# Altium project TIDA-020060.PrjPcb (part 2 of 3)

## Sheet Board_ID_EEPROM.SchDoc
size A4; Date: Not shown in title block; ApprovedBy: Not shown in title block; CheckedBy: Not shown in title block; Author: Not shown in title block; CompanyName: Not shown in title block; Engineer: Not shown in title block; Organization: Not shown in title block; Address1: Not shown in title block; Address2: Not shown in title block; Address3: Not shown in title block; Address4: Not shown in title block; DocumentNumber: 4; Revision: Use project parameter SCH_Rev; SheetNumber: 4; SheetTotal: 19; PageSetup: Record=PageOptions¦CenterHorizontal=True¦CenterVertical=True¦PrintScale=0.93¦XCorrection=1.00¦YCorrection=1.00¦PrintKind=0¦BorderSize=5000000¦LeftOffset=0¦BottomOffset=0¦Orientation=2¦PaperLength=1000¦PaperWidth=1000¦Scale=100¦PaperSource=15¦PrintQuality=600¦MediaType=1¦DitherType=10¦PaperKind=Letter¦PrintScaleMode=1
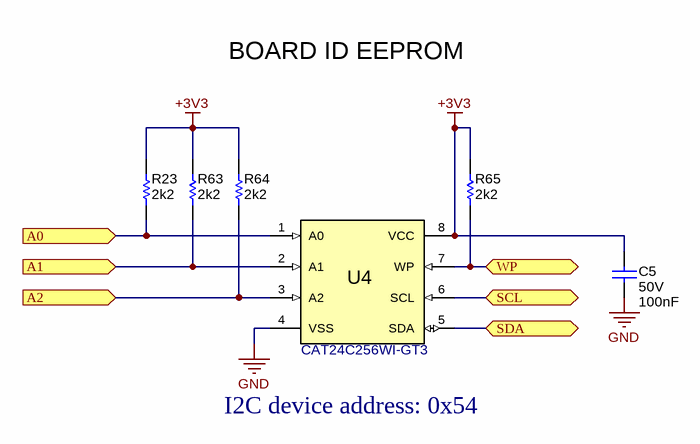
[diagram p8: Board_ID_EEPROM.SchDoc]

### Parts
C5  VDC_V: 50V  ValueDisplayed: 100nF  [0402]  (hidden comment: C1005X5R1H104K050BB)
R23  ValueDisplayed: 2k2  [0402]  (hidden comment: CRCW04022K20JNED)
R63  ValueDisplayed: 2k2  [0402]  (hidden comment: CRCW04022K20JNED)
R64  ValueDisplayed: 2k2  [0402]  (hidden comment: CRCW04022K20JNED)
R65  ValueDisplayed: 2k2  [0402]  (hidden comment: CRCW04022K20JNED)
U4  CAT24C256WI-GT3  [SOIC-8]

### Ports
A0 (in), A1 (in), A2 (in), SCL (bidir), SDA (bidir), WP (bidir)

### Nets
+3V3: C5.2 R23.2 R63.2 R64.2 R65.2 U4.8(VCC)
GND: C5.1 U4.4(VSS)
A0: R23.1 U4.1(A0) ; port A0
A1: R63.1 U4.2(A1) ; port A1
A2: R64.1 U4.3(A2) ; port A2
WKUP_I2C0_SCL: U4.6(SCL) ; port SCL
WKUP_I2C0_SDA: U4.5(SDA) ; port SDA
WP: R65.1 U4.7(WP) ; port WP

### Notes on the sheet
- BOARD ID EEPROM
- I2C device address: 0x54

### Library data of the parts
C5 = CMP-0006279-2: CAP, CERM, 0.1 uF, 50 V, +/- 10%, X5R, 0402; Manufacturer: TDK; TaMin_C: -55°C; ESR_ohm: 0.039064; Polarized: N; SizeAreaWB_mm2: 3; Value1: 0.039064 ohm; U/M: EA; Value: 0.1uF; TaMax_C: 85°C; SizeZ_mm: 0.6; SizeX_mm: 1; SizeY_mm: 0.5; IRMS_A: 814.669mA; AEC Category: Q200
R23 R63-R65 = CMP-0026890-5: RES, 2.2 k, 5%, 0.063 W, AEC-Q200 Grade 0, 0402; Manufacturer: Vishay-Dale; Power_W: 63mW; TempCo: 200 ppm/C; Value_Code: 2k20; Value: 2.2k; EIA_Code: E24; SizeX_mm: 1; SizeY_mm: 0.5; SizeZ_mm: 0.6; Value2: 0.063W; AEC Qualified: Y; VDC_V: 50V; AEC Category: Q200; AEC Grade: 0
U4 = CMP-0005313-2: 256 kb I2C CMOS Serial EEPROM, SOIC-8; Manufacturer: ON Semiconductor; SizeAreaWB_mm2: 55.131; SizeZ_mm: 1.75; SizeX_mm: 5.99; SizeY_mm: 4.9; SizeArea_mm2: 29.351

## Sheet SGMII_caps.SchDoc
size A4; Date: Not shown in title block; ApprovedBy: Not shown in title block; CheckedBy: Not shown in title block; Author: Not shown in title block; CompanyName: Not shown in title block; Engineer: Not shown in title block; Organization: Not shown in title block; Address1: Not shown in title block; Address2: Not shown in title block; Address3: Not shown in title block; Address4: Not shown in title block; DocumentNumber: 11; Revision: Use project parameter SCH_Rev; SheetNumber: 11; SheetTotal: 19; PageSetup: Record=PageOptions¦CenterHorizontal=True¦CenterVertical=True¦PrintScale=0.93¦XCorrection=1.00¦YCorrection=1.00¦PrintKind=0¦BorderSize=5000000¦LeftOffset=0¦BottomOffset=0¦Orientation=2¦PaperLength=1000¦PaperWidth=1000¦Scale=100¦PaperSource=15¦PrintQuality=600¦MediaType=1¦DitherType=10¦PaperKind=Letter¦PrintScaleMode=1
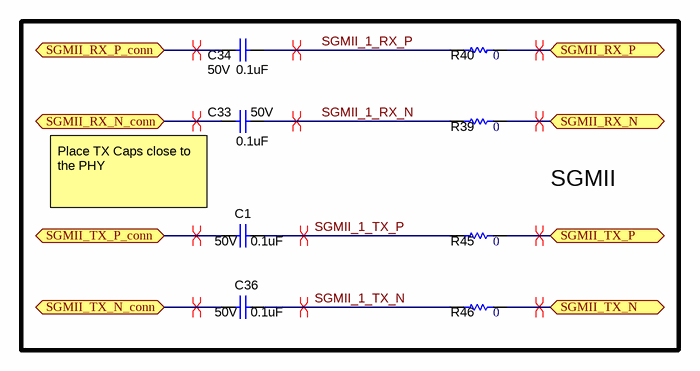
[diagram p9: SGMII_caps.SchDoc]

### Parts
C1  VDC_V: 50V  ValueDisplayed: 0.1uF  [0402S]  (hidden comment: C1005X5R1H104K050BB)
C33  VDC_V: 50V  ValueDisplayed: 0.1uF  [0402S]  (hidden comment: C1005X5R1H104K050BB)
C34  VDC_V: 50V  ValueDisplayed: 0.1uF  [0402S]  (hidden comment: C1005X5R1H104K050BB)
C36  VDC_V: 50V  ValueDisplayed: 0.1uF  [0402S]  (hidden comment: C1005X5R1H104K050BB)
R39  ValueDisplayed: 0  [0402S]  (hidden comment: RK73Z1ETTP)
R40  ValueDisplayed: 0  [0402S]  (hidden comment: RK73Z1ETTP)
R45  ValueDisplayed: 0  [0402S]  (hidden comment: RK73Z1ETTP)
R46  ValueDisplayed: 0  [0402S]  (hidden comment: RK73Z1ETTP)

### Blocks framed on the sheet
SGMII: C1 C33 C34 C36 R39 R40 R45 R46

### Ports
SGMII_RX_N (bidir), SGMII_RX_N_conn (bidir), SGMII_RX_P (bidir), SGMII_RX_P_conn (bidir), SGMII_TX_N (bidir), SGMII_TX_N_conn (bidir), SGMII_TX_P (bidir), SGMII_TX_P_conn (bidir)

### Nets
AE_RX_N: R39.2 ; port SGMII_RX_N
AE_RX_P: R40.2 ; port SGMII_RX_P
AE_TX_N: R46.2 ; port SGMII_TX_N
AE_TX_P: R45.2 ; port SGMII_TX_P
SGMII_1_RX_N: C33.2 R39.1
SGMII_1_RX_P: C34.2 R40.1
SGMII_1_TX_N: C36.2 R46.1
SGMII_1_TX_P: C1.2 R45.1
SGMII_2_RX_N: C33.1 ; port SGMII_RX_N_conn
SGMII_2_RX_P: C34.1 ; port SGMII_RX_P_conn
SGMII_2_TX_N: C36.1 ; port SGMII_TX_N_conn
SGMII_2_TX_P: C1.1 ; port SGMII_TX_P_conn

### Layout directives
differential pair: AE_RX_N, AE_RX_P, AE_TX_N, AE_TX_P, SGMII_1_RX_N, SGMII_1_RX_P, SGMII_1_TX_N, SGMII_1_TX_P, SGMII_2_RX_N, SGMII_2_RX_P, SGMII_2_TX_N, SGMII_2_TX_P

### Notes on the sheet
- Place TX Caps close to the PHY

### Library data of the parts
C1 C33 C34 C36 = CMP-0006279-2: CAP, CERM, 0.1 uF, 50 V, +/- 10%, X5R, 0402; Manufacturer: TDK; TaMin_C: -55°C; ESR_ohm: 39.064m; Polarized: N; SizeAreaWB_mm2: 3; Value1: 0.039064 ohm; U/M: EA; Value: 0.1uF; TaMax_C: 85°C; SizeZ_mm: 0.6; SizeX_mm: 1; SizeY_mm: 0.5; Cap_Case: 0402; Cap_F: 100nF; IRMS_A: 814.669mA; AEC Category: Q200
R39 R40 R45 R46 = CMP-0027007-2: RES, 0, 5%, 0.063 W, AEC-Q200 Grade 0, 0402; Manufacturer: KOA Speer; Power_W: 63mW; TempCo: ppm/C; Value_Code: 0000; Value: 0; SizeX_mm: 1; SizeY_mm: 0.5; SizeZ_mm: 0.6; Value2: 0.063W; AEC Qualified: Y; AEC Category: Q200; EIA_Code: E24; U/M: EA

## Sheet power_indicator_LEDs.SchDoc
size A4; Date: Not shown in title block; ApprovedBy: Not shown in title block; CheckedBy: Not shown in title block; Author: Not shown in title block; CompanyName: Not shown in title block; Engineer: Not shown in title block; Organization: Not shown in title block; Address1: Not shown in title block; Address2: Not shown in title block; Address3: Not shown in title block; Address4: Not shown in title block; DocumentNumber: 12; Revision: Use project parameter SCH_Rev; SheetNumber: 12; SheetTotal: 19; PageSetup: Record=PageOptions¦CenterHorizontal=True¦CenterVertical=True¦PrintScale=0.93¦XCorrection=1.00¦YCorrection=1.00¦PrintKind=0¦BorderSize=5000000¦LeftOffset=0¦BottomOffset=0¦Orientation=2¦PaperLength=1000¦PaperWidth=1000¦Scale=100¦PaperSource=15¦PrintQuality=600¦MediaType=1¦DitherType=10¦PaperKind=Letter¦PrintScaleMode=1
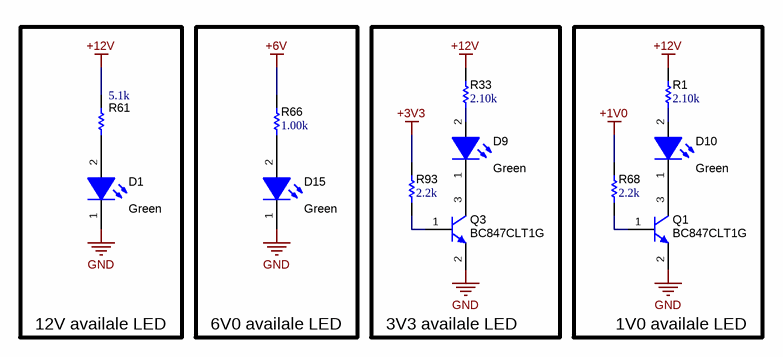
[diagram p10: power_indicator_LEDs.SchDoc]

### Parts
D1  value Green  [LG_M67K_Green]  (hidden comment: LG M67K-G1J2-24-Z)
D9  value Green  [LG_M67K_Green]  (hidden comment: LG M67K-G1J2-24-Z)
D10  value Green  [LG_M67K_Green]  (hidden comment: LG M67K-G1J2-24-Z)
D15  value Green  [LG_M67K_Green]  (hidden comment: LG M67K-G1J2-24-Z)
Q1  BC847CLT1G  [SOT-23]
Q3  BC847CLT1G  [SOT-23]
R1  ValueDisplayed: 2.10k  [0805_HV]  (hidden comment: CRCW08052K10FKEA)
R33  ValueDisplayed: 2.10k  [0805_HV]  (hidden comment: CRCW08052K10FKEA)
R61  Res_ohm: 5.1k  [0805M]  (hidden comment: CRCW08055K10JNEA)
R66  ValueDisplayed: 1.00k  [0805_HV]  (hidden comment: CRCW08051K00FKEA)
R68  ValueDisplayed: 2.2k  [0402]  (hidden comment: CRCW04022K20JNED)
R93  ValueDisplayed: 2.2k  [0402]  (hidden comment: CRCW04022K20JNED)

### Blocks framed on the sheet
12V availale LED: D1 R61
6V0 availale LED: D15 R66
3V3 availale LED: D9 Q3 R33 R93
1V0 availale LED: D10 Q1 R1 R68

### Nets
+1V0: R68.1
+3V3: R93.1
+6V: R66.2
+12V: R1.2 R33.2 R61.2
GND: D1.1(K) D15.1(K) Q1.2(E) Q3.2(E)
NetD1_2: D1.2(A) R61.1
NetD9_1: D9.1(K) Q3.3(C)
NetD9_2: D9.2(A) R33.1
NetD10_1: D10.1(K) Q1.3(C)
NetD10_2: D10.2(A) R1.1
NetD15_2: D15.2(A) R66.1
NetQ1_1: Q1.1(B) R68.2
NetQ3_1: Q3.1(B) R93.2

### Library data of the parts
D1 D9 D10 D15 = CMP-0002971-3: LED, Green, SMD; Manufacturer: OSRAM; Value2: 1.8V; Type: AlInGaP; Io_A: 2mA; Tjmax_C: 125°C; Value1: W; Vr_V: 12V; Angle: 120
Q1 Q3 = CMP-0000376-2: Transistor, NPN, 45 V, 0.1 A, SOT-23; Manufacturer: ON Semiconductor; TaMax_C: 150°C; Value2: 800; Value1: 0.1 A; Vcesat1_V: 7dV; SizeX_mm: 2.5; SizeY_mm: 3; TaMin_C: -55°C; IcRated_A: 1dA; CompType: BJT; SizeZ_mm: 1.1; Value: 45 V; SizeArea_mm2: 7.5; NPN: 1; Vceo_V: 45V; PNP: 0; AEC Category: Q101; SizeAreaWB_mm2: 14; U/M: EA
R1 R33 = CMP-0021108-3: RES, 2.10 k, 1%, 0.125 W, AEC-Q200 Grade 0, 0805; Manufacturer: Vishay-Dale; Power_W: 125mW; TempCo: 100 ppm/C; Value_Code: 2k10; Value: 2.10k; EIA_Code: E96; Res_ohm: 2.1k; SizeX_mm: 2; SizeY_mm: 1.25; SizeZ_mm: 1.45; Value2: 0.125W; SizeArea_mm2: 2.5; AEC Qualified: Y; VDC_V: 150V; AEC Category: Q200; AEC Grade: 0
R61 = CMP-0020572-3: RES, 5.1 k, 5%, 0.125 W, AEC-Q200 Grade 0, 0805; Manufacturer: Vishay-Dale; Power_W: 125mW; TempCo: 200 ppm/C; SizeZ_mm: 1.45; AEC Qualified: Y; VDC_V: 150V; AEC Grade: 0; AEC Category: Q200; EIA_Code: E24; SizeArea_mm2: 2.5; SizeX_mm: 2; SizeY_mm: 1.25; Value2: 0.125W; Value: 5.1k; Value_Code: 5k10
R66 = CMP-0020951-3: RES, 1.00 k, 1%, 0.125 W, AEC-Q200 Grade 0, 0805; Manufacturer: Vishay-Dale; Power_W: 125mW; TempCo: 100 ppm/C; Value_Code: 1k00; Value: 1.00k; EIA_Code: E96; Res_ohm: 1k; SizeX_mm: 2; SizeY_mm: 1.25; SizeZ_mm: 1.45; Value2: 0.125W; SizeArea_mm2: 2.5; AEC Qualified: Y; VDC_V: 150V; AEC Category: Q200; AEC Grade: 0
R68 R93 = CMP-0026890-5: as R23 on sheet Board_ID_EEPROM

## Sheet 1V0_LDO.SchDoc
size A4; Date: Not shown in title block; ApprovedBy: Not shown in title block; CheckedBy: Not shown in title block; Author: Not shown in title block; CompanyName: Not shown in title block; Engineer: Not shown in title block; Organization: Not shown in title block; Address1: Not shown in title block; Address2: Not shown in title block; Address3: Not shown in title block; Address4: Not shown in title block; DocumentNumber: 10; Revision: Use project parameter SCH_Rev; SheetNumber: 10; SheetTotal: 19; PageSetup: Record=PageOptions¦CenterHorizontal=True¦CenterVertical=True¦PrintScale=0.93¦XCorrection=1.00¦YCorrection=1.00¦PrintKind=0¦BorderSize=5000000¦LeftOffset=0¦BottomOffset=0¦Orientation=2¦PaperLength=1000¦PaperWidth=1000¦Scale=100¦PaperSource=15¦PrintQuality=600¦MediaType=1¦DitherType=10¦PaperKind=Letter¦PrintScaleMode=1
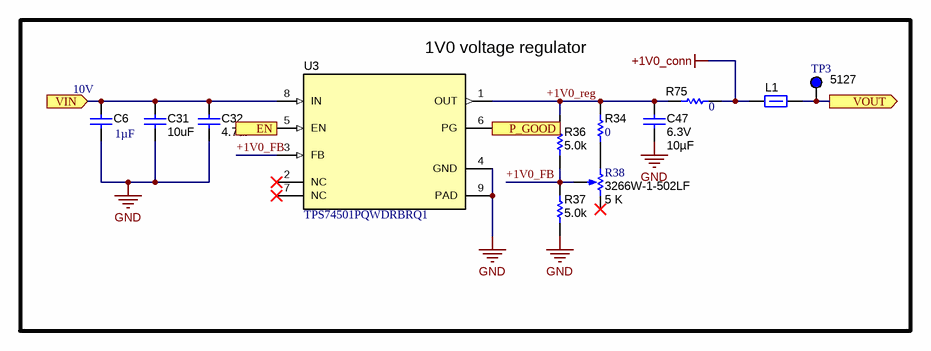
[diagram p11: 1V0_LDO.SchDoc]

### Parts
C6  ValueDisplayed: 1µF  VDC_V: 10V  [0402]  (hidden comment: GRT155C71A105KE13D)
C31  ValueDisplayed: 10uF  [0805_HV]  (hidden comment: GRM21BC71E106KE11L)
C32  ValueDisplayed: 4.7uF  [0603]  (hidden comment: C1608X7S1A475K080AC)
C47  VDC_V: 6.3V  Cap_F: 10µF  [0603]  (hidden comment: CL10B106MQ8NRNC)
L1  BLM18AG102SN1D  [0603]  (value not drawn)
R34  ValueDisplayed: 0  [0402]  (hidden comment: RK73Z1ETTP)
R36  ValueDisplayed: 5.0k  [0402]  (hidden comment: CRCW04024K42FKED)
R37  ValueDisplayed: 5.0k  [0402]  (hidden comment: CRCW04024K42FKED)
R38  3266W-1-502LF  value 5 K  [TRIM_3266W]
R75  ValueDisplayed: 0  [0402]  (hidden comment: RK73Z1ETTP)
TP3  5127  [Keystone5127]
U3  TPS74501PQWDRBRQ1  [DRB0008J]

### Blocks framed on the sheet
1V0 voltage regulator: C6 C31 C32 C47 L1 R34 R36-R38 R75 TP3 U3

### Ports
EN (in), P_GOOD (out), VIN (in), VOUT (out)

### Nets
+1V0: L1.2 TP3.1 ; port VOUT
+1V0_conn: L1.1 R75.2
+3V3: C6.1 C31.2 C32.2 U3.5(EN) U3.8(IN) ; port VIN, port EN
GND: C6.2 C31.1 C32.1 C47.2 R37.1 U3.4(GND) U3.9(PAD)
+1V0_FB: R36.1 R37.2 R38.2(WIPER) U3.3(FB)
+1V0_reg: C47.1 R34.1 R36.2 R75.1 U3.1(OUT)
PG_1V: U3.6(PG) ; port P_GOOD
NetR34_2: R34.2 R38.1(CCW)

Not connected (* = marked no-connect by the designer): R38 3(CW)*; U3 2(NC)* 7(NC)*

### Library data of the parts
C6 = CMP-0085818-1: CAP, CERM, 1 µF, 10 V,+/- 10%, X7S, AEC-Q200 Grade 1, 0402; Manufacturer: MuRata; TaMin_C: -55°C; Polarized: N; SizeAreaWB_mm2: 3; U/M: EA; Value: 1uF; TaMax_C: 125°C; SizeZ_mm: 0.6; SizeX_mm: 1; SizeY_mm: 0.5; AEC Qualified: Y; AEC Category: Q200
C31 = CMP-0008262-2: CAP, CERM, 10 uF, 25 V, +/- 10%, X7S, 0805; Manufacturer: MuRata; TaMin_C: -55°C; Polarized: N; SizeAreaWB_mm2: 6.75; Value1: Unknown; U/M: EA; Value: 10uF; TaMax_C: 125°C; SizeZ_mm: 1.45; SizeX_mm: 2; SizeY_mm: 1.25; Cap_Case: 0805; Value2: 25V; SizeArea_mm2: 2.5; Cap_F: 10µF; AEC Category: Q200
C32 = CMP-0007058-4: CAP, CERM, 4.7 uF, 10 V, +/- 10%, X7S, 0603; Manufacturer: TDK; TaMin_C: -55°C; Polarized: N; SizeAreaWB_mm2: 4.68; Value1: Unknown; U/M: EA; Value: 4.7uF; TaMax_C: 125°C; SizeZ_mm: 1; SizeX_mm: 1.6; SizeY_mm: 0.8; Value2: 10V; SizeArea_mm2: 1.28; Cap_F: 4.7µF; AEC Category: Q200
C47 = CMP-0084301-1: CAP, CERM, 10 µF, 6.3 V,+/- 20%, X7R, 0603; Manufacturer: Samsung Electro-Mechanics; SizeY_mm: 0.8; SizeAreaWB_mm2: 4.68; SizeX_mm: 1.6; SizeArea_mm2: 1.28; AEC Qualified: N; Value: 10uF; U/M: EA; SizeZ_mm: 1; TaMax_C: 125°C; AEC Category: Q200; TaMin_C: -55°C
L1 = CMP-0003343-2: Ferrite Bead, 1000 ohm @ 100 MHz, 0.4 A, 0603; Manufacturer: MuRata; ZTyp@100MHz_Ohm: 1k; SizeAreaWB_mm2: 4.68; DCR_ohm: 0.5; Value1: 0.5 ohm; Imax_A: 400mA; SizeZ_mm: 1; SizeX_mm: 1.6; SizeY_mm: 0.8; Value2: 0.4A; SizeArea_mm2: 1.28
R34 R75 = CMP-0027007-2: RES, 0, 5%, 0.063 W, AEC-Q200 Grade 0, 0402; Manufacturer: KOA Speer; Power_W: 63mW; TempCo: ppm/C; Value_Code: 0000; Value: 0; EIA_Code: E24; SizeX_mm: 1; SizeY_mm: 0.5; SizeZ_mm: 0.6; Value2: 0.063W; AEC Qualified: Y; AEC Category: Q200; U/M: EA
R36 R37 = CMP-0026409-2: RES, 5.0k, 1%, 0.063 W, AEC-Q200 Grade 0, 0402; Manufacturer: Vishay-Dale; Power_W: 63mW; TempCo: 100 ppm/C; Value_Code: 4k42; EIA_Code: E96; Res_ohm: 4.42k; SizeX_mm: 1; SizeY_mm: 0.5; SizeZ_mm: 0.6; Value2: 0.063W; AEC Qualified: Y; VDC_V: 50V; AEC Category: Q200; AEC Grade: 0
R38 = CMP-0002067-2: Trimmer, 5k ohm, 0.25W, TH; Manufacturer: Bourns
TP3 = CMP-0055156-2: Test Point, Multipurpose, Blue, TH; Manufacturer: Keystone Electronics; CNHeader: FALSE; Green_Lifecycle: Active; Green_REACh: Passed; ContactFinish: Silver; CT: TRUE
U3 = CMP-0860764-1: 500-mA LDO With Power-Good in Small Wettable Flank WSON Package, DRB0008J (VSON-8); Manufacturer: Texas Instruments; SizeZ_mm: 1; SizeAreaWB_mm2: 16; CompType: IC; SizeArea_mm2: 9; SizeY_mm: 3; AEC Category: Q200; AEC Qualified: Y

## Sheet PSE.SchDoc
size A4; Date: Not shown in title block; ApprovedBy: Not shown in title block; CheckedBy: Not shown in title block; Author: Not shown in title block; CompanyName: Not shown in title block; Engineer: Not shown in title block; Organization: Not shown in title block; Address1: Not shown in title block; Address2: Not shown in title block; Address3: Not shown in title block; Address4: Not shown in title block; DocumentNumber: 14; Revision: Use project parameter SCH_Rev; SheetNumber: 14; SheetTotal: 19; PageSetup: Record=PageOptions¦CenterHorizontal=True¦CenterVertical=True¦PrintScale=0.93¦XCorrection=1.00¦YCorrection=1.00¦PrintKind=0¦BorderSize=5000000¦LeftOffset=0¦BottomOffset=0¦Orientation=2¦PaperLength=1000¦PaperWidth=1000¦Scale=100¦PaperSource=15¦PrintQuality=600¦MediaType=1¦DitherType=10¦PaperKind=Letter¦PrintScaleMode=1
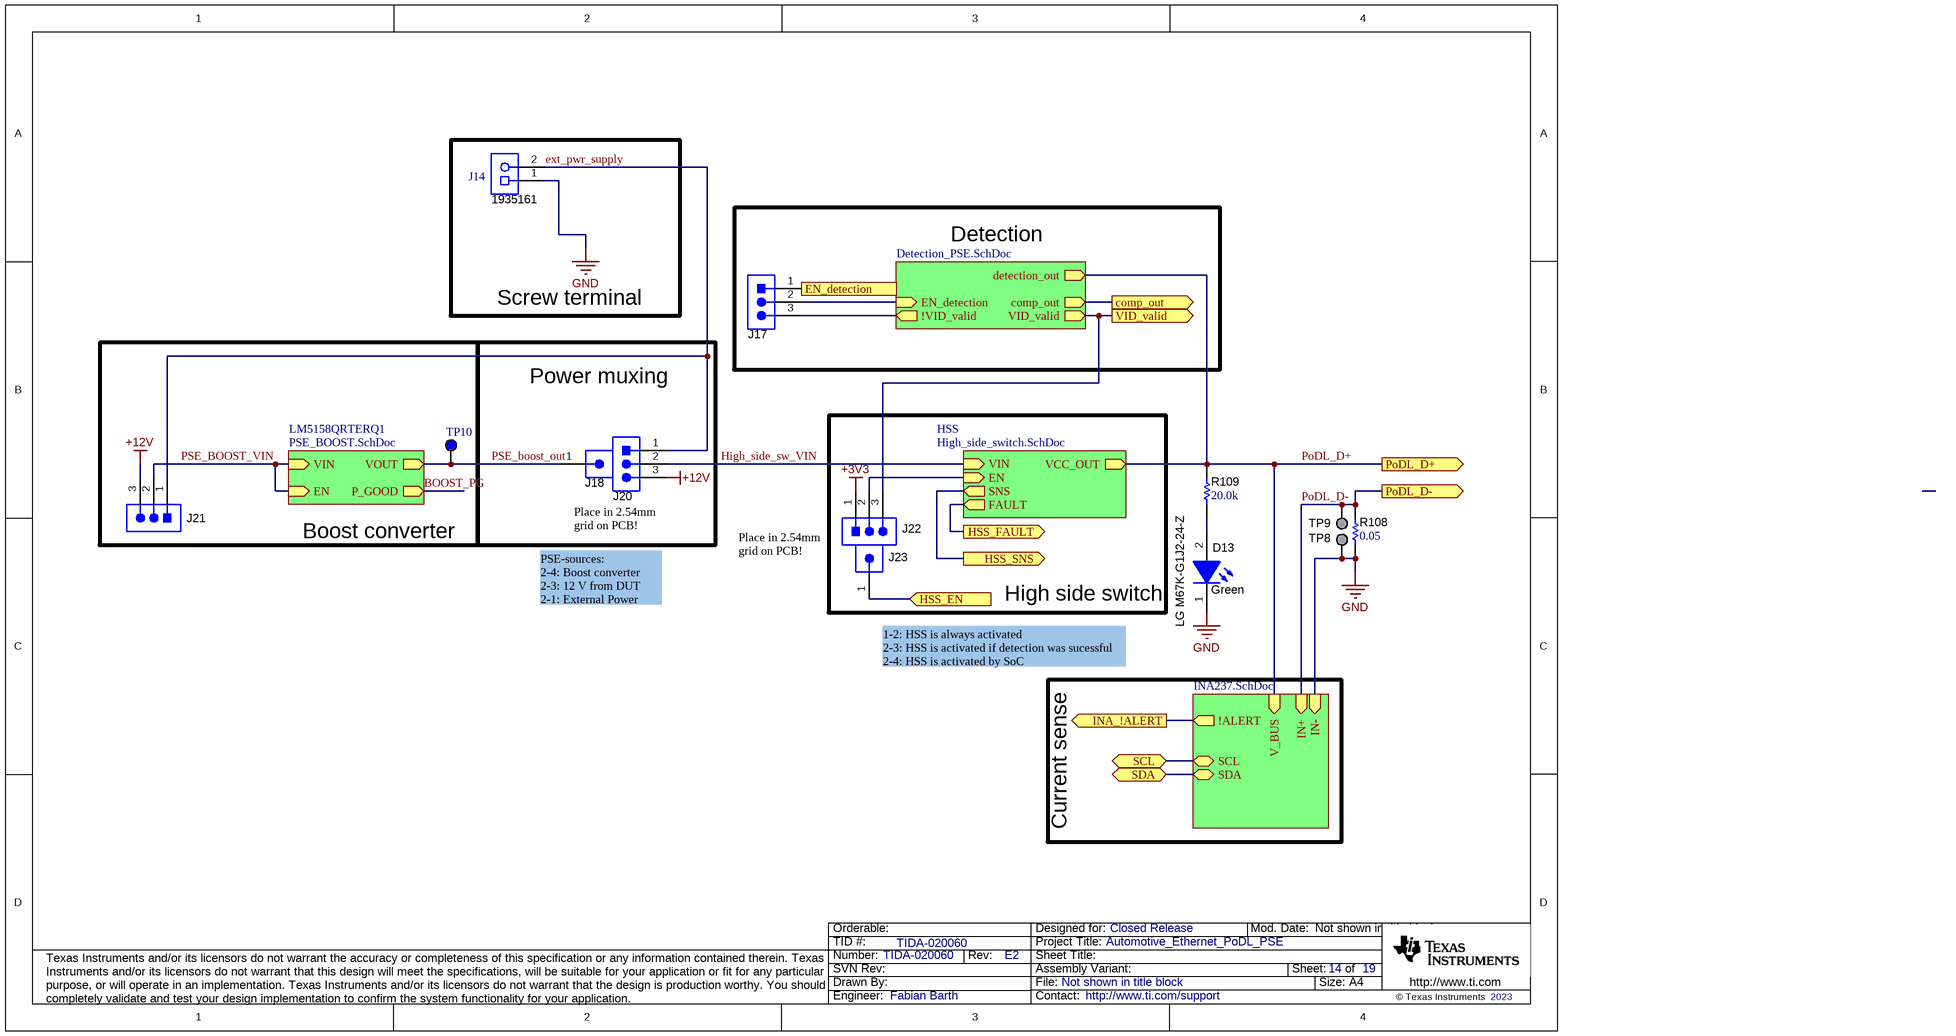
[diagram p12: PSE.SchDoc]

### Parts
D13  LG M67K-G1J2-24-Z  value Green  [LG_M67K_Green]
J14  1935161  [Phoenix_1935161]
J17  TSW-103-07-G-S  [TSW-103-07-G-S]  (value not drawn)
J18  TSW-101-07-G-S  [TSW-101-07-G-S]  (value not drawn)
J20  TSW-103-07-G-S  [TSW-103-07-G-S]  (value not drawn)
J21  TSW-103-07-G-S  [TSW-103-07-G-S]  (value not drawn)
J22  TSW-103-07-G-S  [TSW-103-07-G-S]  (value not drawn)
J23  TSW-101-07-G-S  [TSW-101-07-G-S]  (value not drawn)
R108  ValueDisplayed: 0.05  [0612]  (hidden comment: ERJ-B2CFR05V)
R109  ValueDisplayed: 20.0k  [0402]  (hidden comment: RT0402BRD0720KL)
TP8  TP_SM_1MM  [TP_SM_1MM]  (value not drawn)  (no BOM)
TP9  TP_SM_1MM  [TP_SM_1MM]  (value not drawn)  (no BOM)
TP10  5127  [Keystone5127]  (value not drawn)

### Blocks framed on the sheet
Screw terminal: J14
Detection: J17
Boost converter: J21 TP10
Power muxing: J18 J20
High side switch: J22 J23

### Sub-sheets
current_sense_sheet = INA237.SchDoc: IN+ (in), IN- (in), V_BUS (in), SDA (bidir), SCL (bidir), !ALERT (out)
Detections_sheet = Detection_PSE.SchDoc: detection_out (out), EN_detection (in), comp_out (out), !VID_valid (out), VID_valid (out)
HSS = High_side_switch.SchDoc: VIN (in), VCC_OUT (out), EN (in), FAULT (out), SNS (out)
LM5158QRTERQ1 = PSE_BOOST.SchDoc: EN (in), VIN (in), VOUT (out), P_GOOD (out)

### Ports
comp_out (out), EN_detection (out), HSS_EN (in), HSS_FAULT (out), HSS_SNS (out), INA_!ALERT (out), PoDL_D+ (out), PoDL_D- (out), SCL (bidir), SDA (bidir), VID_valid (out)

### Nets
+3V3: J22.1
+12V: J20.3 J21.3
GND: D13.1(K) J14.1 R108.1 TP8.1 ; sheet current_sense_sheet/IN-
!ALERT: port INA_!ALERT, sheet current_sense_sheet/!ALERT
comp_out: port comp_out, sheet Detections_sheet/comp_out
EN: J22.2 ; sheet HSS/EN
EN_detection: J17.2 ; sheet Detections_sheet/EN_detection
EN_detection_SoC: J17.1 ; port EN_detection
ext_pwr_supply: J14.2 J20.1 J21.1
High_side_sw_VIN: J20.2 ; sheet HSS/VIN
HSS_EN: J23.1 ; port HSS_EN
HSS_FAULT: port HSS_FAULT, sheet HSS/FAULT
HSS_SNS: port HSS_SNS, sheet HSS/SNS
PoDL_D+: R109.2 ; port PoDL_D+, sheet HSS/VCC_OUT, sheet Detections_sheet/detection_out, sheet current_sense_sheet/V_BUS
PoDL_D-: R108.2 TP9.1 ; port PoDL_D-, sheet current_sense_sheet/IN+
PSE_boost_out: J18.1 TP10.1 ; sheet LM5158QRTERQ1/VOUT
PSE_BOOST_VIN: J21.2 ; sheet LM5158QRTERQ1/EN, sheet LM5158QRTERQ1/VIN
Q: J22.3 ; port VID_valid, sheet Detections_sheet/VID_valid
Q_N: J17.3 ; sheet Detections_sheet/!VID_valid
SCL: port SCL, sheet current_sense_sheet/SCL
SDA: port SDA, sheet current_sense_sheet/SDA
NetD13_2: D13.2(A) R109.1

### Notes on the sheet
- Place in 2.54mm grid on PCB!
- PSE-sources:
  2-4: Boost converter
  2-3: 12 V from DUT
  2-1: External Power
- 1-2: HSS is always activated
  2-3: HSS is activated if detection was sucessful
  2-4: HSS is activated by SoC
- Current sense

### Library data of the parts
D13 = CMP-0002971-3: as D1 on sheet power_indicator_LEDs
J14 = CMP-0055502-1: Therminal Block, 5 mm, 2-pole, TH; Manufacturer: Phoenix Contact; CT: TRUE; CompType: Terminal Block; CNHeader: FALSE
J17 J20-J22 = CMP-0075407-2: Header, 100mil, 3x1, Gold, TH; Manufacturer: Samtec; Pitch_mm: 2.54; Cert_VDE: N; Gender: Male; Cert_CSA: Y; Voltage_V: 550V; Green_REACh: Passed; Current_A: 6.3A; Green_Lifecycle: Active; Row_Count: 1
J18 J23 = CMP-0075403-1: Header, 100mil, 1pos, Gold, TH; Manufacturer: Samtec; Cert_VDE: N; CNHeader: True; Current_A: 6.3A; Green_Lifecycle: Active; Gender: Male; Cert_CSA: Y; Green_REACh: Passed; Voltage_V: 550V; Row_Count: 1; Pitch_mm: 2.54; CT: False
R108 = CMP-0015056-3: RES, 0.05, 1%, 1 W, AEC-Q200 Grade 0, 0612; Manufacturer: Panasonic; Value: 0.05; Res_ohm: 50m; Power_W: 1W; SizeY_mm: 3.2; AEC Grade: 0; SizeArea_mm2: 5.12; SizeAreaWB_mm2: 10.92; AEC Category: Q200; TempCo: 150 ppm/C; SizeZ_mm: 0.85; SizeX_mm: 1.6; Value_Code: R050; AEC Qualified: Y; U/M: EA; EIA_Code: E96
R109 = CMP-0065358-1: RES, 20.0 k, .1%, .0625 W, 0402; Manufacturer: Yageo America; Power_W: 62.5mW; TempCo: 25 ppm/C; Value_Code: 20k0; U/M: EA; Value: 20.0k; EIA_Code: E192; Tolerance_%: 0.1%; Res_ohm: 20k; SizeX_mm: 1.0; SizeY_mm: 0.5; SizeZ_mm: 0.6; Value2: .0625W; VDC_V: 50V; AEC Category: Q200
TP8 TP9 = CMP-0003825-1: 1mm Test Point, SMT; Manufacturer: Any
TP10 = CMP-0055156-2: as TP3 on sheet 1V0_LDO

## Sheet High_side_switch.SchDoc
size A4; Date: Not shown in title block; ApprovedBy: Not shown in title block; CheckedBy: Not shown in title block; Author: Not shown in title block; CompanyName: Not shown in title block; Engineer: Not shown in title block; Organization: Not shown in title block; Address1: Not shown in title block; Address2: Not shown in title block; Address3: Not shown in title block; Address4: Not shown in title block; DocumentNumber: 18; Revision: Use project parameter SCH_Rev; SheetNumber: 18; SheetTotal: 19; PageSetup: Record=PageOptions¦CenterHorizontal=True¦CenterVertical=True¦PrintScale=0.93¦XCorrection=1.00¦YCorrection=1.00¦PrintKind=0¦BorderSize=5000000¦LeftOffset=0¦BottomOffset=0¦Orientation=2¦PaperLength=1000¦PaperWidth=1000¦Scale=100¦PaperSource=15¦PrintQuality=600¦MediaType=1¦DitherType=10¦PaperKind=Letter¦PrintScaleMode=1
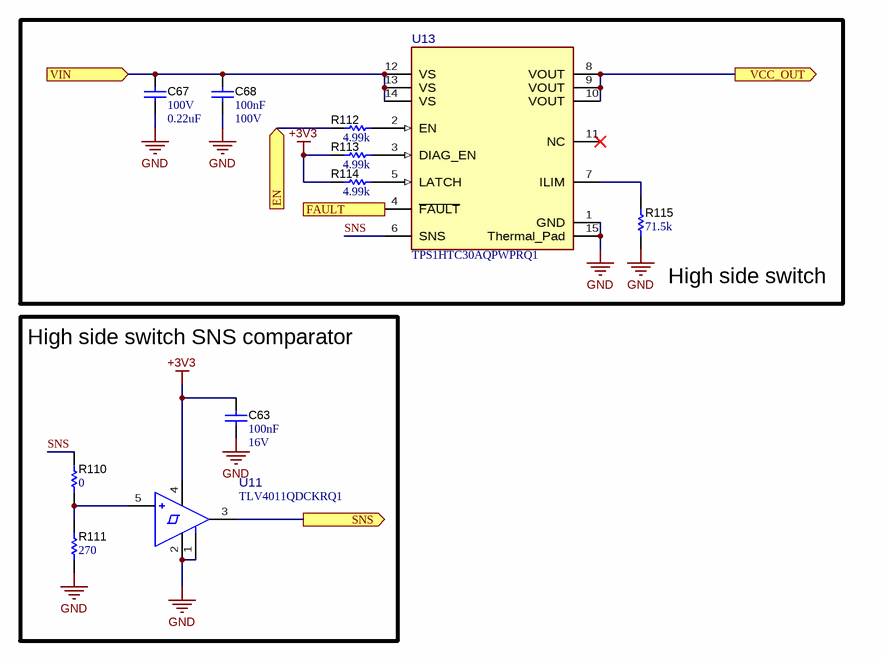
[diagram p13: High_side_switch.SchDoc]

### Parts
C63  Cap_F: 100nF  VDC_V: 16V  [0402S]  (hidden comment: C0402C104K4RACAUTO)
C67  VDC_V: 100V  ValueDisplayed: 0.22uF  [0805_HV1]  (hidden comment: GRM21AR72A224KAC5L)
C68  Cap_F: 100nF  VDC_V: 100V  [0603S]  (hidden comment: GRM188R72A104KA35D)
R110  ValueDisplayed: 0  [0402]  (hidden comment: RK73Z1ETTP)
R111  ValueDisplayed: 270  [0603S]  (hidden comment: CRCW0603270RJNEA)
R112  ValueDisplayed: 4.99k  [0402S]  (hidden comment: RC0402FR-074K99L)
R113  ValueDisplayed: 4.99k  [0402S]  (hidden comment: RC0402FR-074K99L)
R114  ValueDisplayed: 4.99k  [0402S]  (hidden comment: RC0402FR-074K99L)
R115  ValueDisplayed: 71.5k  [0402S]  (hidden comment: ERJ-2RKF7152X)
U11  TLV4011QDCKRQ1  [DCK0005A-MFG]
U13  TPS1HTC30AQPWPRQ1  [PWP0014C-MFG]

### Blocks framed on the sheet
High side switch: C67 C68 R112-R115 U13
High side switch SNS comparator: C63 R110 R111 U11

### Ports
EN (in), FAULT (out), SNS (out), VCC_OUT (out), VIN (in)

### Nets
+3V3: C63.1 R113.1 R114.1 U11.4(VDD)
GND: C63.2 C67.2 C68.2 R111.1 R115.1 U11.1(NC) U11.2(GND) U13.1(GND) U13.15(Thermal_Pad)
EN: R112.1 ; port EN
High_side_sw_VIN: C67.1 C68.1 U13.12(VS) U13.13(VS) U13.14(VS) ; port VIN
HSS_FAULT: U13.4(~{FAULT}) ; port FAULT
HSS_SNS: U11.3(~{RESET}) ; port SNS
PoDL_D+: U13.8(VOUT) U13.9(VOUT) U13.10(VOUT) ; port VCC_OUT
SNS: R110.2 U13.6(SNS)
NetR110_1: R110.1 R111.2 U11.5(SENSE)
NetR112_2: R112.2 U13.2(EN)
NetR113_2: R113.2 U13.3(DIAG_EN)
NetR114_2: R114.2 U13.5(LATCH)
NetR115_2: R115.2 U13.7(ILIM)

Not connected (* = marked no-connect by the designer): U13 11(NC)*

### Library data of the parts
C63 = CMP-0006237-2: CAP, CERM, 0.1 uF, 16 V, +/- 10%, X7R, AEC-Q200 Grade 1, 0402; Manufacturer: Kemet; TaMin_C: -55°C; Polarized: N; SizeAreaWB_mm2: 3; Value1: Unknown; U/M: EA; Value: 0.1uF; TaMax_C: 125°C; SizeZ_mm: 0.6; SizeX_mm: 1; SizeY_mm: 0.5; Cap_Case: 0402; AEC Qualified: Y; AEC Category: Q200
C67 = CMP-0008249-2: CAP, CERM, 0.22 uF, 100 V, +/- 10%, X7R, 0805; Manufacturer: MuRata; TaMin_C: -55°C; Polarized: N; SizeAreaWB_mm2: 6.75; U/M: EA; Value: 0.22uF; TaMax_C: 125°C; SizeZ_mm: 1.45; SizeX_mm: 2; SizeY_mm: 1.25; Cap_Case: 0805; SizeArea_mm2: 2.5; Cap_F: 220nF; AEC Category: Q200; Value1: Unknown
C68 = CMP-0007469-4: CAP, CERM, 0.1 uF, 100 V, +/- 10%, X7R, 0603; Manufacturer: MuRata; TaMin_C: -55°C; Polarized: N; SizeAreaWB_mm2: 4.68; Value1: Unknown; U/M: EA; Value: 0.1uF; TaMax_C: 125°C; SizeZ_mm: 1; SizeX_mm: 1.6; SizeY_mm: 0.8; Cap_Case: 0603; SizeArea_mm2: 1.28; AEC Category: Q200
R110 = CMP-0027007-2: as R39 on sheet SGMII_caps
R111 = CMP-0025765-4: RES, 270, 5%, 0.1 W, AEC-Q200 Grade 0, 0603; Manufacturer: Vishay-Dale; Power_W: 100mW; TempCo: 200 ppm/C; Value_Code: 270R; Value: 270; SizeX_mm: 1.6; SizeY_mm: 0.8; SizeZ_mm: 1; Value2: 0.1W; SizeArea_mm2: 1.28; AEC Qualified: Y; VDC_V: 75V; AEC Category: Q200; AEC Grade: 0; EIA_Code: E24
R112-R114 = CMP-0026740-1: RES, 4.99 k, 1%, 0.063 W, 0402; Manufacturer: Yageo America; Power_W: 63mW; TempCo: 100 ppm/C; Value_Code: 4k99; U/M: EA; Value: 4.99k; EIA_Code: E96; SizeX_mm: 1; SizeY_mm: 0.5; SizeZ_mm: 0.6; Value2: 0.063W; AEC Qualified: N; VDC_V: 50V; AEC Category: Q200
R115 = CMP-0026709-1: RES, 71.5 k, 1%, 0.1 W, AEC-Q200 Grade 0, 0402; Manufacturer: Panasonic; Power_W: 100mW; TempCo: 100 ppm/C; Value_Code: 71k5; U/M: EA; Value: 71.5k; EIA_Code: E96; SizeX_mm: 1; SizeY_mm: 0.5; SizeZ_mm: 0.6; Value2: 0.1W; AEC Qualified: Y; VDC_V: 50V; AEC Category: Q200; AEC Grade: 0
U11 = CMP-0120009-1: Low-Power Comparator with Precision Reference; Manufacturer: Texas Instruments; Nominal Supply Current: 2uA; TaMax_C: +125°C; Number Of Channels: 1; Standoff Height: 0mm; AEC Qualified: Yes; SizeZ_mm: 1.1mm; Max Supply Voltage: 6V; TaMin_C: -40°C; Min Supply Voltage: 1.3V; AEC Grade: Grade 1
U13 = CMP-0097835-1: 30-mΩ, 24-V, 6-A Single-Channel Automotive Smart High-Side Switch; Manufacturer: Texas Instruments; Min Supply Voltage: 6V; Number Of Outputs: 1; Nominal Supply Current: 0.98-1mA; TaMin_C: -40°C; TaMax_C: +125°C; SizeZ_mm: 1.2mm; AEC Grade: Grade 1; Max Supply Voltage: 48V; AEC Qualified: Yes; Standoff Height: 0.05mm

## Sheet PSE_BOOST.SchDoc
size A4; Date: Not shown in title block; ApprovedBy: Not shown in title block; CheckedBy: Not shown in title block; Author: Not shown in title block; CompanyName: Not shown in title block; Engineer: Not shown in title block; Organization: Not shown in title block; Address1: Not shown in title block; Address2: Not shown in title block; Address3: Not shown in title block; Address4: Not shown in title block; DocumentNumber: 16; Revision: Use project parameter SCH_Rev; SheetNumber: 16; SheetTotal: 19; PageSetup: Record=PageOptions¦CenterHorizontal=True¦CenterVertical=True¦PrintScale=0.93¦XCorrection=1.00¦YCorrection=1.00¦PrintKind=0¦BorderSize=5000000¦LeftOffset=0¦BottomOffset=0¦Orientation=2¦PaperLength=1000¦PaperWidth=1000¦Scale=100¦PaperSource=15¦PrintQuality=600¦MediaType=1¦DitherType=10¦PaperKind=Letter¦PrintScaleMode=1
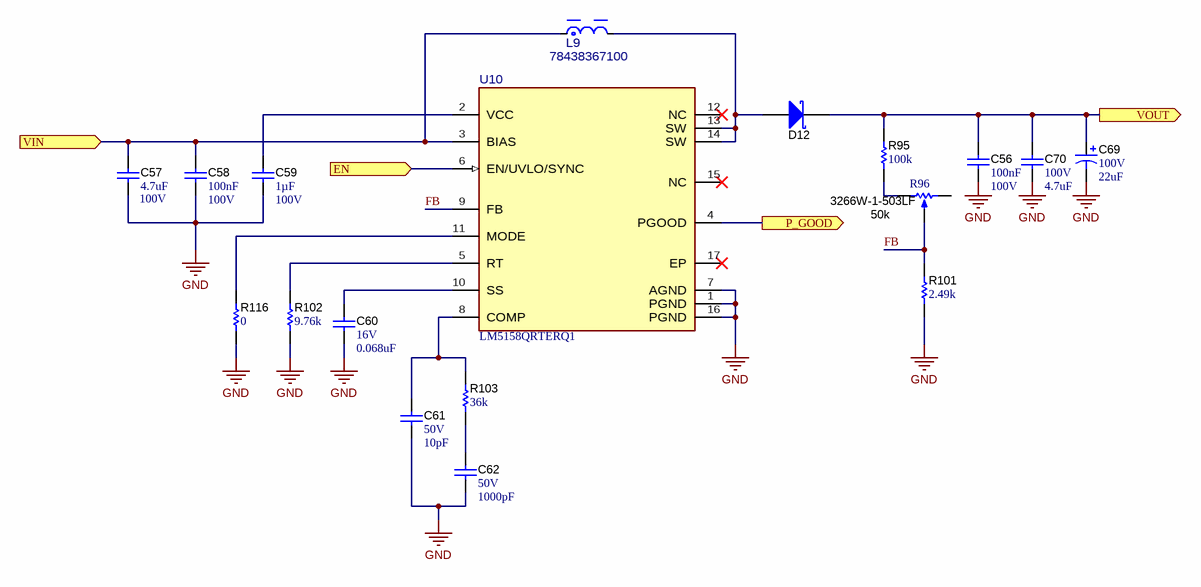
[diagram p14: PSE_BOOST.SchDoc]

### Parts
C56  Cap_F: 100nF  VDC_V: 100V  [0805_HV]  (hidden comment: C2012X7R2A104K125AA)
C57  VDC_V: 100V  ValueDisplayed: 4.7uF  [1210_220]  (hidden comment: GRM32DC72A475KE01L)
C58  Cap_F: 100nF  VDC_V: 100V  [0603]  (hidden comment: GRM188R72A104KA35D)
C59  Cap_F: 1µF  VDC_V: 100V  [0805_HV]  (hidden comment: CGA4J3X7S2A105K125AB)
C60  VDC_V: 16V  ValueDisplayed: 0.068uF  [0402S]  (hidden comment: GRM155R71C683KA88D)
C61  VDC_V: 50V  ValueDisplayed: 10pF  [0805_HV]  (hidden comment: C0805C100J5GACTU)
C62  VDC_V: 50V  ValueDisplayed: 1000pF  [0402S]  (hidden comment: CGA2B2X8R1H102K050BA)
C69  VDC_V: 100V  ValueDisplayed: 22uF  [SM_RADIAL_F]  (hidden comment: EEE-FK2A220P)
C70  VDC_V: 100V  ValueDisplayed: 4.7uF  [1210_220]  (hidden comment: GRM32DC72A475KE01L)
D12  PMEG6020ER,115  [SOD-123W]  (value not drawn)
L9  78438367100  [FP-78438367100_SMT_IND_5MM4_5MM4-MFG]
R95  ValueDisplayed: 100k  [0603S]  (hidden comment: CRCW0603100KDHEAP)
R96  3266W-1-503LF  value 50k  [TRIM_3266W]
R101  ValueDisplayed: 2.49k  [0402S]  (hidden comment: CRCW04022K49FKED)
R102  ValueDisplayed: 9.76k  [0402S]  (hidden comment: CRCW04029K76FKED)
R103  ValueDisplayed: 36k  [0402S]  (hidden comment: CRCW040236K0JNED)
R116  ValueDisplayed: 0  [0402S]  (hidden comment: RK73Z1ETTP)
U10  LM5158QRTERQ1  [RTE0016K-MFG]

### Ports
EN (in), P_GOOD (out), VIN (in), VOUT (out)

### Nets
GND: C56.2 C57.2 C58.2 C59.2 C60.2 C61.2 C62.2 C69.2(-) C70.2 R101.1 R102.1 R116.1 U10.1(PGND) U10.7(AGND) U10.16(PGND)
BOOST_PG: U10.4(PGOOD) ; port P_GOOD
FB: R96.2(WIPER) R101.2 U10.9(FB)
PSE_boost_out: C56.1 C69.1(+) C70.1 D12.1(K) R95.2 ; port VOUT
PSE_BOOST_VIN: C57.1 C58.1 L9.1 U10.3(BIAS) U10.6(EN/UVLO/SYNC) ; port VIN, port EN
NetC59_1: C59.1 U10.2(VCC)
NetC60_1: C60.1 U10.10(SS)
NetC61_1: C61.1 R103.2 U10.8(COMP)
NetC62_1: C62.1 R103.1
NetD12_2: D12.2(A) L9.2 U10.13(SW) U10.14(SW)
NetR95_1: R95.1 R96.1(CCW)
NetR102_2: R102.2 U10.5(RT)
NetR116_2: R116.2 U10.11(MODE)

Not connected (* = marked no-connect by the designer): R96 3(CW); U10 12(NC)* 15(NC)* 17(EP)*

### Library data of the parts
C56 = CMP-0007886-2: CAP, CERM, 0.1 uF, 100 V, +/- 10%, X7R, 0805; Manufacturer: TDK; TaMin_C: -55°C; ESR_ohm: 0.020726; Polarized: N; SizeAreaWB_mm2: 6.75; Value1: 0.020726 ohm; U/M: EA; Value: 0.1uF; TaMax_C: 125°C; SizeZ_mm: 1.45; SizeX_mm: 2; SizeY_mm: 1.25; Cap_Case: 0805; SizeArea_mm2: 2.5; IRMS_A: 1.456A; AEC Category: Q200
C57 C70 = CMP-0009182-2: CAP, CERM, 4.7 uF, 100 V, +/- 10%, X7S, 1210; Manufacturer: MuRata; TaMin_C: -55°C; Polarized: N; SizeAreaWB_mm2: 14.7; Value1: Unknown; U/M: EA; Value: 4.7uF; TaMax_C: 125°C; SizeZ_mm: 2.2; SizeX_mm: 3.2; SizeY_mm: 2.5; Cap_Case: 1210; SizeArea_mm2: 8; Cap_F: 4.7µF; AEC Category: Q200
C58 = CMP-0007469-4: CAP, CERM, 0.1 uF, 100 V, +/- 10%, X7R, 0603; Manufacturer: MuRata; TaMin_C: -55°C; Polarized: N; SizeAreaWB_mm2: 4.68; Value1: Unknown; U/M: EA; Value: 0.1uF; TaMax_C: 125°C; SizeZ_mm: 1; SizeX_mm: 1.6; SizeY_mm: 0.8; SizeArea_mm2: 1.28; AEC Category: Q200
C59 = CMP-0007980-2: CAP, CERM, 1 uF, 100 V, +/- 10%, X7S, AEC-Q200 Grade 1, 0805; Manufacturer: TDK; TaMin_C: -55°C; Polarized: N; SizeAreaWB_mm2: 6.75; Value1: 0.008255 ohm; U/M: EA; Value: 1uF; TaMax_C: 125°C; SizeZ_mm: 1.45; SizeX_mm: 2; SizeY_mm: 1.25; Cap_Case: 0805; SizeArea_mm2: 2.5; AEC Qualified: Y; AEC Grade: 1; AEC Category: Q200; ESR_ohm: 8.255m; IRMS_A: 2.2744A
C60 = CMP-0006655-2: CAP, CERM, 0.068 uF, 16 V, +/- 10%, X7R, 0402; Manufacturer: MuRata; TaMin_C: -55°C; Polarized: N; SizeAreaWB_mm2: 3; Value1: Unknown; U/M: EA; TaMax_C: 125°C; SizeZ_mm: 0.6; SizeX_mm: 1; SizeY_mm: 0.5; Cap_Case: 0402; Cap_F: 68nF; AEC Category: Q200
C61 = CMP-0007704-2: CAP, CERM, 10 pF, 50 V, +/- 5%, C0G/NP0, 0805; Manufacturer: Kemet; TaMin_C: -55°C; ESR_ohm: 0.285; Polarized: N; SizeAreaWB_mm2: 6.75; Value1: 0.285 ohm; U/M: EA; Value: 10pF; TaMax_C: 125°C; SizeZ_mm: 1.45; SizeX_mm: 2; SizeY_mm: 1.25; Cap_Case: 0805; SizeArea_mm2: 2.5; IRMS_A: 221mA; AEC Category: Q200
C62 = CMP-0860997-1: CAP, CERM, 1000 pF, 50 V,+/- 10%, X8R, AEC-Q200 Grade 0, 0402; Manufacturer: TDK; TaMin_C: -55°C; Polarized: N; SizeAreaWB_mm2: 3; U/M: EA; Value: 1000pF; TaMax_C: 150°C; SizeZ_mm: 0.6; SizeX_mm: 1; SizeY_mm: 0.5; Cap_Case: 0402; AEC Qualified: Y; Cap_F: 1nF; AEC Category: Q200; AEC Grade: 0
C69 = CMP-0011202-2: CAP, AL, 22 uF, 100 V, +/- 20%, 1.3 ohm, AEC-Q200 Grade 2, SMD; Manufacturer: Panasonic; TaMin_C: -55°C; ESR_ohm: 1.3; Polarized: Y; SizeAreaWB_mm2: 123.6; Value1: 1.3 ohm; U/M: EA; Value: 22uF; TaMax_C: 105°C; SizeZ_mm: 10.2; SizeX_mm: 10; SizeY_mm: 8.3; Cap_Case: F; SizeArea_mm2: 83; CompType: Capacitor; Cap_F: 22µF; IRMS_A: 130mA; AEC Category: Q200; AEC Grade: 2
D12 = CMP-0076989-2: Diode, Schottky, 60 V, 2 A, SOD-123W; Manufacturer: Nexperia; AEC Category: Q101; Vr_V: 60V; TJmax_C: 150°C; Green_Lifecycle: Not Set; Value1: 2A; SizeZ_mm: 1.0; Vf_V: 530mV; SizeY_mm: 1.7; Value2: 0.53V; Value: 60V; SizeArea_mm2: 5.95; SizeAreaWB_mm2: 12.15; Green_REACh: Incomplete; SizeX_mm: 3.5
L9 = CMP-0098310-1: 10 µH Shielded Inductor 3.3 A 70.2mOhm Max Nonstandard; Manufacturer: Wurth Electronics; AEC Grade: Grade 1; AEC Qualified: Yes; DCR_ohm: 70.2m; Ind_H: 10µH; Irms: 3.3A; Isat: 4.8A; Material: Iron Alloy; SizeZ_mm: 3.1mm; Value: 10uH; Self Resonant Frequency: 13MHz; Shrouded: true; TaMax_C: +85°C; TaMin_C: -40°C; Test Frequency: 100kHz; Tolerance_%: 20%
R95 = CMP-0086261-1: RES, 100 k, 0.5%, 0.1 W, AEC-Q200 Grade 0, 0603; Manufacturer: Vishay-Dale; Power_W: 100mW; TempCo: 50 ppm/C; Value: 100k; EIA_Code: E192; SizeX_mm: 1.6; SizeY_mm: 0.8; SizeZ_mm: 1; Value2: 0.1W; SizeArea_mm2: 1.28; AEC Qualified: Y; AEC Grade: 0; AEC Category: Q200; SizeAreaWB_mm2: 4.68
R96 = CMP-0002069-2: Trimmer, 50k ohm, 0.25W, TH; Manufacturer: Bourns
R101 = CMP-0026237-2: RES, 2.49 k, 1%, 0.063 W, AEC-Q200 Grade 0, 0402; Manufacturer: Vishay-Dale; Power_W: 63mW; TempCo: 100 ppm/C; Value_Code: 2k49; Value: 2.49k; EIA_Code: E96; SizeX_mm: 1; SizeY_mm: 0.5; SizeZ_mm: 0.6; Value2: 0.063W; AEC Qualified: Y; VDC_V: 50V; AEC Category: Q200; AEC Grade: 0
R102 = CMP-0026622-3: RES, 9.76 k, 1%, 0.063 W, AEC-Q200 Grade 0, 0402; Manufacturer: Vishay-Dale; AEC Category: Q200; AEC Qualified: Y; AEC Grade: 0; Value2: 0.063W; Value_Code: 9k76; SizeY_mm: 0.5; SizeZ_mm: 0.6; VDC_V: 50V; SizeX_mm: 1; Value: 9.76k; Power_W: 63mW; EIA_Code: E96; TempCo: 100 ppm/C
R103 = CMP-0026911-3: RES, 36 k, 5%, 0.063 W, AEC-Q200 Grade 0, 0402; Manufacturer: Vishay-Dale; Power_W: 63mW; TempCo: 200 ppm/C; Value_Code: 36k0; Value: 36k; EIA_Code: E24; SizeX_mm: 1; SizeY_mm: 0.5; SizeZ_mm: 0.6; Value2: 0.063W; AEC Qualified: Y; VDC_V: 50V; AEC Grade: 0; AEC Category: Q200
R116 = CMP-0027007-2: as R39 on sheet SGMII_caps
U10 = CMP-0091836-5: 2.2-MHz Wide VIN 85-V Boost/Sepic/Flyback Converter with Dual Random Spread Spectrum; Manufacturer: Texas Instruments; Output Type: AdjustableProgrammable; Number Of Outputs: 1; Output Voltage: 83V; Standoff Height: 0mm; AEC Qualified: Yes; Max Duty Cycle: 96%; Switching Frequency: 100-2200kHz; AEC Grade: Grade 1; Max Supply Voltage: 60V; TJmax_C: +150°C; Min Supply Voltage: 1.5V; AEC Category: Q200; TaMax_C: +125°C; Nominal Supply Current: 670uA; TaMin_C: -40°C; Switching Topology: Boost,Flyback; SizeZ_mm: 0.8mm; CompType: IC

## Sheet Detection_PSE.SchDoc
size A4; Date: Not shown in title block; ApprovedBy: Not shown in title block; CheckedBy: Not shown in title block; Author: Not shown in title block; CompanyName: Not shown in title block; Engineer: Not shown in title block; Organization: Not shown in title block; Address1: Not shown in title block; Address2: Not shown in title block; Address3: Not shown in title block; Address4: Not shown in title block; DocumentNumber: 15; Revision: Use project parameter SCH_Rev; SheetNumber: 15; SheetTotal: 19; PageSetup: Record=PageOptions¦CenterHorizontal=True¦CenterVertical=True¦PrintScale=0.93¦XCorrection=1.00¦YCorrection=1.00¦PrintKind=0¦BorderSize=5000000¦LeftOffset=0¦BottomOffset=0¦Orientation=2¦PaperLength=1000¦PaperWidth=1000¦Scale=100¦PaperSource=15¦PrintQuality=600¦MediaType=1¦DitherType=10¦PaperKind=Letter¦PrintScaleMode=1
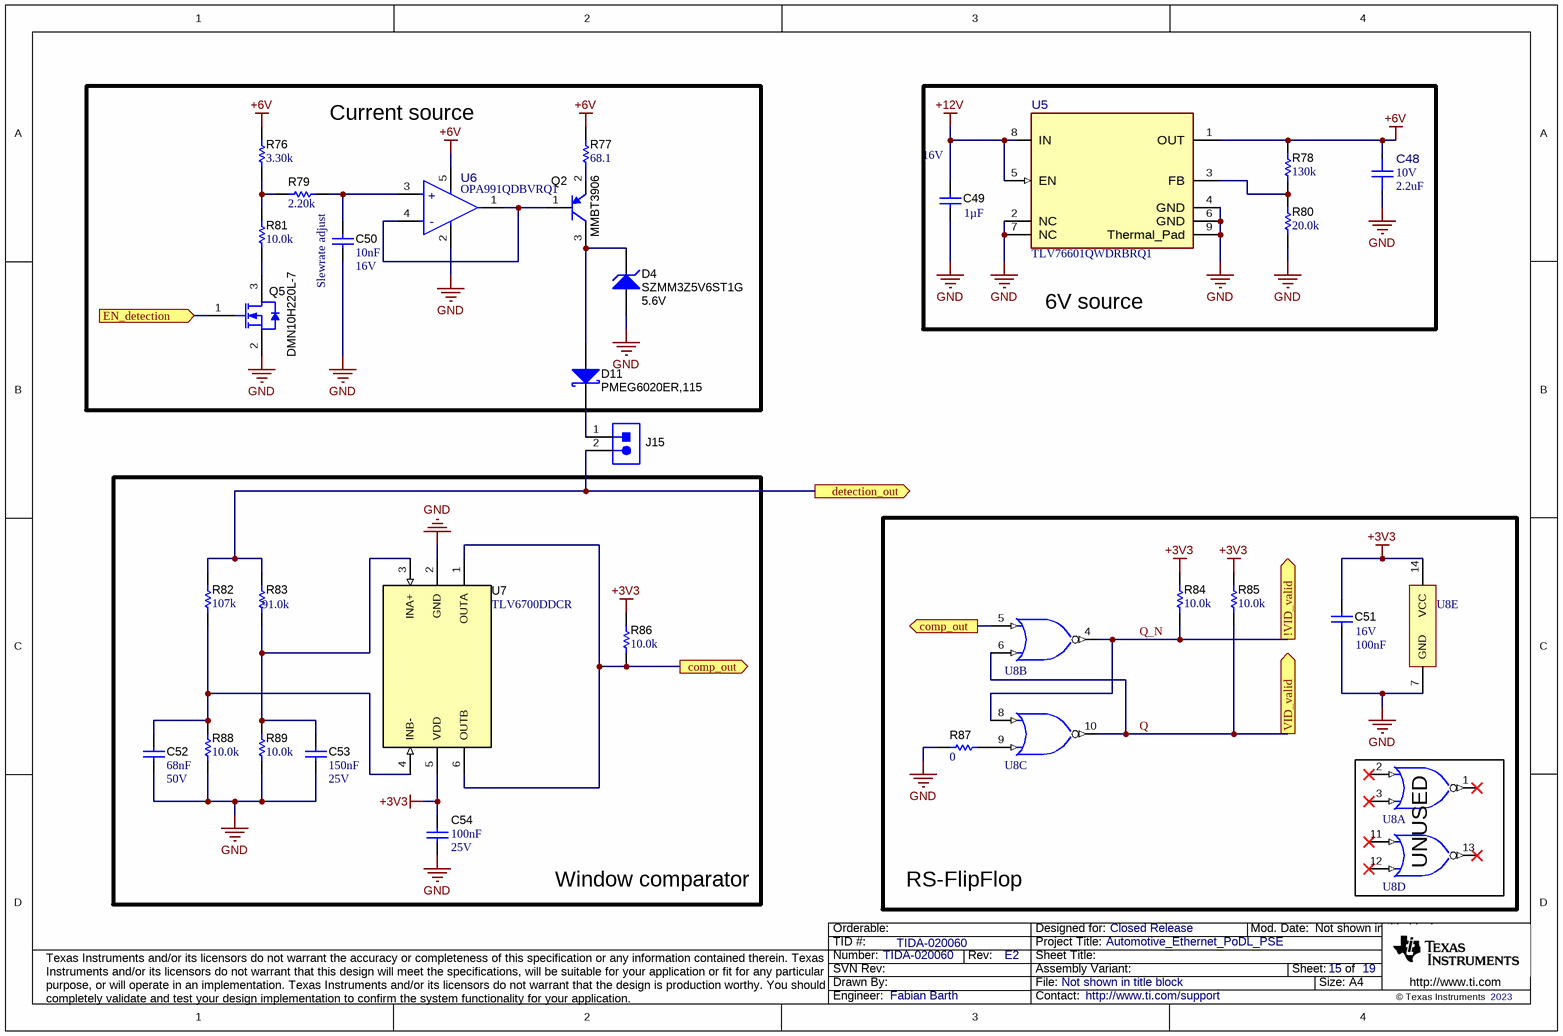
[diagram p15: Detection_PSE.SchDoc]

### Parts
C48  VDC_V: 10V  ValueDisplayed: 2.2uF  [FP-C0603C225M8PAC7867_0603-MFG]  (hidden comment: C0603C225M8PAC7867)
C49  ValueDisplayed: 1µF  VDC_V: 16V  [0402S]  (hidden comment: GRM155R61C105MA12D)
C50  Cap_F: 10nF  VDC_V: 16V  [0603]  (hidden comment: 885012206040)
C51  Cap_F: 100nF  VDC_V: 16V  [0402S]  (hidden comment: C0402C104K4RACAUTO)
C52  Cap_F: 68nF  VDC_V: 50V  [0603]  (hidden comment: CGA3E2X7R1H683K080AA)
C53  Cap_F: 150nF  VDC_V: 25V  [0603]  (hidden comment: GRM188R71E154KA01D)
C54  Cap_F: 100nF  VDC_V: 25V  [0603]  (hidden comment: 885012206071)
D4  SZMM3Z5V6ST1G  value 5.6V  [SOD-323]
D11  PMEG6020ER,115  [SOD-123W]
J15  TSW-102-07-G-S  [TSW-102-07-G-S]  (value not drawn)
Q2  MMBT3906  [SOT-23]
Q5  DMN10H220L-7  [SOT-23]
R76  ValueDisplayed: 3.30k  [0603]  (hidden comment: RC0603FR-073K3L)
R77  ValueDisplayed: 68.1  [0603]  (hidden comment: RC0603FR-0768R1L)
R78  ValueDisplayed: 130k  [0402]  (hidden comment: CRCW0402130KFKED)
R79  ValueDisplayed: 2.20k  [0603]  (hidden comment: RC0603FR-072K2L)
R80  ValueDisplayed: 20.0k  [0402]  (hidden comment: RT0402BRD0720KL)
R81  ValueDisplayed: 10.0k  [0603]  (hidden comment: RT0603DRE0710KL)
R82  ValueDisplayed: 107k  [0603]  (hidden comment: RT0603DRE07107KL)
R83  ValueDisplayed: 91.0k  [0603]  (hidden comment: RG1608P-913-B-T5)
R84  ValueDisplayed: 10.0k  [0402]  (hidden comment: RMCF0402FT10K0)
R85  ValueDisplayed: 10.0k  [0402]  (hidden comment: RMCF0402FT10K0)
R86  ValueDisplayed: 10.0k  [0402]  (hidden comment: RMCF0402FT10K0)
R87  ValueDisplayed: 0  [0402S]  (hidden comment: CRCW04020000Z0EDHP)
R88  ValueDisplayed: 10.0k  [0603]  (hidden comment: RT0603DRE0710KL)
R89  ValueDisplayed: 10.0k  [0603]  (hidden comment: RT0603DRE0710KL)
U5  TLV76601QWDRBRQ1  [DRB0008J-MFG]
U6  OPA991QDBVRQ1  [DBV0005A-MFG]
U7  TLV6700DDCR  [DDC0006A_N]
U8  SN74AHC02QPWRQ1  [PW0014A_N]  (value not drawn)  (parts A,B,C,D,E of 5)

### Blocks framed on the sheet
Current source: C50 D4 D11 Q2 Q5 R76 R77 R79 R81 U6
6V source: C48 C49 R78 R80 U5
Window comparator: C52-C54 R82 R83 R86 R88 R89 U7
RS-FlipFlop: C51 R84 R85 R87 U8
UNUSED: U8

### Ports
!VID_valid (out), comp_out (out), detection_out (out), EN_detection (in), VID_valid (out)

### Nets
+3V3: C51.1 C54.2 R84.2 R85.2 R86.2 U7.5(VDD) U8.14(VCC)
+6V: C48.2 R76.2 R77.2 R78.2 U5.1(OUT) U6.5(V+)
+12V: C49.1 U5.5(EN) U5.8(IN)
GND: C48.1 C49.2 C50.2 C51.2 C52.2 C53.2 C54.1 D4.2(A) Q5.2(S) R80.1 R87.1 R88.1 R89.1 U5.2(NC) U5.4(GND) U5.6(GND) U5.7(NC) U5.9(Thermal_Pad) U6.2(V-) U7.2(GND) U8.7(GND)
comp_out: R86.1 U7.1(OUTA) U7.6(OUTB) U8.5(2A) ; port comp_out
EN_detection: Q5.1(G) ; port EN_detection
PoDL_D+: J15.2 R82.2 R83.2 ; port detection_out
Q: R85.1 U8.6(2B) U8.10(3Y) ; port VID_valid
Q_N: R84.1 U8.4(2Y) U8.8(3A) ; port !VID_valid
NetC50_1: C50.1 R79.2 U6.3(IN+)
NetC52_1: C52.1 R82.1 R88.2 U7.4(INB-)
NetC53_1: C53.1 R83.1 R89.2 U7.3(INA+)
NetD4_1: D4.1(K) D11.2(A) Q2.3(C)
NetD11_1: D11.1(K) J15.1
NetQ2_1: Q2.1(B) U6.1(OUT) U6.4(IN-)
NetQ2_2: Q2.2(E) R77.1
NetQ5_3: Q5.3(D) R81.1
NetR76_1: R76.1 R79.1 R81.2
NetR78_1: R78.1 R80.2 U5.3(FB)
NetR87_2: R87.2 U8.9(3B)

Not connected (* = marked no-connect by the designer): U8 1(1Y)* 2(1A)* 3(1B)* 11(4A)* 12(4B)* 13(4Y)*

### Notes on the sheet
- (near R79) Slewrate adjust

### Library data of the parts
C48 = CMP-0120003-1: 2.2 µF ±20% 10V Ceramic Capacitor X5R 0603 (1608 Metric); Manufacturer: KEMET; TempCo: 15%; Value: 2.2µF; SizeZ_mm: 0.9mm; AEC Qualified: No
C49 = CMP-0084375-1: CAP, CERM, 1 µF, 16 V,+/- 20%, X5R, 0402; Manufacturer: MuRata; TaMin_C: -55°C; Polarized: N; SizeAreaWB_mm2: 3; U/M: EA; Value: 1uF; TaMax_C: 85°C; SizeZ_mm: 0.6; SizeX_mm: 1; SizeY_mm: 0.5; Cap_Case: 0402; AEC Category: Q200
C50 = CMP-0006828-4: CAP, CERM, 0.01 uF, 16 V, +/- 10%, X7R, 0603; Manufacturer: Wurth Elektronik; TaMin_C: -55°C; Polarized: N; SizeAreaWB_mm2: 4.68; Value1: Unknown; U/M: EA; Value: 0.01uF; TaMax_C: 125°C; SizeZ_mm: 1; SizeX_mm: 1.6; SizeY_mm: 0.8; SizeArea_mm2: 1.28; AEC Category: Q200
C51 = CMP-0006237-2: CAP, CERM, 0.1 uF, 16 V, +/- 10%, X7R, AEC-Q200 Grade 1, 0402; Manufacturer: Kemet; SizeAreaWB_mm2: 3; SizeArea_mm2: 0.5; AEC Qualified: Y; AEC Category: Q200; Value: 0.1uF; TaMax_C: 125°C; SizeZ_mm: 0.6; AEC Grade: 1; Polarized: N; TaMin_C: -55°C; U/M: EA; Cap_Case: 0402; Value1: Unknown
C52 = CMP-0007080-5: CAP, CERM, 0.068 uF, 50 V, +/- 10%, X7R, AEC-Q200 Grade 1, 0603; Manufacturer: TDK; TaMin_C: -55°C; ESR_ohm: 0.035979; Polarized: N; SizeAreaWB_mm2: 4.68; Value1: 0.035979 ohm; U/M: EA; TaMax_C: 125°C; SizeZ_mm: 1; SizeX_mm: 1.6; SizeY_mm: 0.8; SizeArea_mm2: 1.28; AEC Qualified: Y; IRMS_A: 8.86483dA; AEC Category: Q200
C53 = CMP-0007411-4: CAP, CERM, 0.15 uF, 25 V, +/- 10%, X7R, 0603; Manufacturer: MuRata; SizeAreaWB_mm2: 4.68; SizeArea_mm2: 1.28; AEC Category: Q200; Value: 0.15uF; TaMax_C: 125°C; SizeZ_mm: 1; Polarized: N; TaMin_C: -55°C; SizeY_mm: 0.8; U/M: EA; SizeX_mm: 1.6; Value1: Unknown
C54 = CMP-0006832-5: CAP, CERM, 0.1 uF, 25 V, +/- 10%, X7R, 0603; Manufacturer: Wurth Elektronik; TaMin_C: -55°C; Polarized: N; SizeAreaWB_mm2: 4.68; Value1: Unknown; U/M: EA; Value: 0.1uF; TaMax_C: 125°C; SizeZ_mm: 1; SizeX_mm: 1.6; SizeY_mm: 0.8; SizeArea_mm2: 1.28; AEC Category: Q200
D4 = CMP-0085742-1: Diode, Zener, 5.6 V, 300 mW, AEC-Q101, SOD-323; Manufacturer: ON Semiconductor; SizeAreaWB_mm2: 8.695; SizeY_mm: 1.35; SizeZ_mm: 1; AEC Qualified: Y; SizeArea_mm2: 3.645; Value1: 0.3W; Power_W: 300mW; RJA_CperW: 416; AEC Category: Q101; SizeX_mm: 2.7
D11 = CMP-0076989-2: as D12 on sheet PSE_BOOST
J15 = CMP-0075405-3: Header, 100mil, 2x1, Gold, TH; Manufacturer: Samtec; Current_A: 6.3A; Green_Lifecycle: Active; Pitch_mm: 2.54; Cert_CSA: Y; Cert_VDE: N; Green_REACh: Passed; Row_Count: 1; Gender: Male; Voltage_V: 550V
Q2 = CMP-0000325-2: Transistor, PNP, 40 V, 0.2 A, SOT-23; Manufacturer: Fairchild Semiconductor; TaMax_C: 150°C; Value2: 300; Value1: 0.2 A; Vcesat1_V: 250mV; SizeX_mm: 2.5; SizeY_mm: 3; TaMin_C: -55°C; IcRated_A: 200mA; CompType: BJT; SizeZ_mm: 1.1; Value: 40 V; SizeArea_mm2: 7.5; NPN: 0; Vceo_V: 40V; PNP: 1; AEC Category: Q101; SizeAreaWB_mm2: 14; U/M: EA
Q5 = CMP-0000971-2: MOSFET, N-CH, 100 V, 1.4 A, SOT-23; Alternate Manufacturer: None; Manufacturer: Diodes Inc.; SizeZ_mm: 1.1; ChType: N; Value2: 4.1 nC; Value1: 0.2; VdsMax_V: 100V; SizeX_mm: 2.5; SizeY_mm: 3; Vgs_V: 16V; Value: 100V; Rdson45_ohm: 2.5d; SizeArea_mm2: 7.5; AEC Category: Q101; IdsMax_A: 1.4A; SizeAreaWB_mm2: 14; U/M: EA; QgTyp_nC: 4.1
R76 = CMP-0023081-5: RES, 3.30 k, 1%, 0.1 W, 0603; Manufacturer: Yageo; Power_W: 100mW; TempCo: 100 ppm/C; Value_Code: 3k30; Value: 3.30k; Res_ohm: 3.3k; SizeX_mm: 1.6; SizeY_mm: 0.8; SizeZ_mm: 1; Value2: 0.1W; SizeArea_mm2: 1.28; AEC Qualified: N; VDC_V: 75V; AEC Category: Q200; SizeAreaWB_mm2: 4.68
R77 = CMP-0023240-5: RES, 68.1, 1%, 0.1 W, 0603; Manufacturer: Yageo; Power_W: 100mW; TempCo: 100 ppm/C; Value_Code: 68R1; Value: 68.1; EIA_Code: E96; SizeX_mm: 1.6; SizeY_mm: 0.8; SizeZ_mm: 1; Value2: 0.1W; SizeArea_mm2: 1.28; AEC Qualified: N; VDC_V: 75V; AEC Category: Q200; SizeAreaWB_mm2: 4.68
R78 = CMP-0025997-3: RES, 130 k, 1%, 0.063 W, AEC-Q200 Grade 0, 0402; Manufacturer: Vishay-Dale; Power_W: 63mW; TempCo: 100 ppm/C; Value: 130k; EIA_Code: E96; SizeX_mm: 1; SizeY_mm: 0.5; SizeZ_mm: 0.6; Value2: 0.063W; AEC Qualified: Y; VDC_V: 50V; AEC Category: Q200; AEC Grade: 0
R79 = CMP-0022986-5: RES, 2.20 k, 1%, 0.1 W, 0603; Manufacturer: Yageo; Power_W: 100mW; TempCo: 100 ppm/C; Value_Code: 2k20; Value: 2.20k; Res_ohm: 2.2k; SizeX_mm: 1.6; SizeY_mm: 0.8; SizeZ_mm: 1; Value2: 0.1W; SizeArea_mm2: 1.28; AEC Qualified: N; VDC_V: 75V; AEC Category: Q200; SizeAreaWB_mm2: 4.68
R80 = CMP-0065358-1: as R109 on sheet PSE
R81 = CMP-0024586-3: RES, 10.0 k, 0.5%, 0.1 W, 0603; Manufacturer: Yageo America; Power_W: 100mW; TempCo: 50 ppm/C; Value_Code: 10k0; Value: 10.0k; EIA_Code: E192; Res_ohm: 10k; SizeX_mm: 1.6; SizeY_mm: 0.8; SizeZ_mm: 1; Value2: 0.1W; SizeArea_mm2: 1.28; VDC_V: 75V; AEC Category: Q200; U/M: EA
R82 = CMP-0024575-3: RES, 107 k, 0.5%, 0.1 W, 0603; Manufacturer: Yageo America; Power_W: 100mW; TempCo: 50 ppm/C; U/M: EA; Value: 107k; EIA_Code: E192; SizeX_mm: 1.6; SizeY_mm: 0.8; SizeZ_mm: 1; Value2: 0.1W; SizeArea_mm2: 1.28; VDC_V: 75V; AEC Category: Q200
R83 = CMP-0023620-3: RES, 91.0 k, 0.1%, 0.1 W, 0603; Manufacturer: Susumu Co Ltd; Power_W: 100mW; TempCo: 25 ppm/C; Value_Code: 91k0; U/M: EA; Value: 91.0k; Res_ohm: 91k; SizeX_mm: 1.6; SizeY_mm: 0.8; SizeZ_mm: 1; Value2: 0.1W; SizeArea_mm2: 1.28; VDC_V: 75V; AEC Category: Q200
R84-R86 = CMP-0026754-1: RES, 10.0 k, 1%, 0.063 W, AEC-Q200 Grade 0, 0402; Manufacturer: Stackpole Electronics Inc; Power_W: 63mW; TempCo: 100 ppm/C; Value_Code: 10k0; U/M: EA; Value: 10.0k; EIA_Code: E96; Res_ohm: 10k; SizeX_mm: 1; SizeY_mm: 0.5; SizeZ_mm: 0.6; Value2: 0.063W; AEC Qualified: Y; VDC_V: 50V; AEC Grade: 0; AEC Category: Q200
R87 = CMP-0081856-1: RES, 0, 0%, 0.2 W, AEC-Q200 Grade 0, 0402; Manufacturer: Vishay-Dale; Power_W: 200mW; Value: 0; SizeX_mm: 1; SizeY_mm: 0.5; SizeZ_mm: 0.6; Value2: 0.2W; AEC Qualified: Y; AEC Category: Q200; VDC_V: 50V; SizeAreaWB_mm2: 3
R88 R89 = CMP-0024586-3: RES, 10.0 k, 0.5%, 0.1 W, 0603; Manufacturer: Yageo America; Power_W: 100mW; TempCo: 50 ppm/C; Value_Code: 10k0; U/M: EA; Value: 10.0k; EIA_Code: E192; Res_ohm: 10k; SizeX_mm: 1.6; SizeY_mm: 0.8; SizeZ_mm: 1; Value2: 0.1W; SizeArea_mm2: 1.28; VDC_V: 75V; AEC Category: Q200
U5 = CMP-0092470-1: Automotive, adjustable- and fixed-output, 500-mA, 16-V, positive-voltage, LDO linear regulator 8-SON -40 to 150; Manufacturer: Texas Instruments; Output Type: AdjustableProgrammable; Standoff Height: 0mm; Min Supply Voltage: 2.5V; Number Of Outputs: 1; AEC Qualified: Yes; Max Supply Voltage: 16V; Nominal Supply Current: 50uA; AEC Grade: Grade 1; TaMax_C: +125°C; SizeZ_mm: 1mm; TaMin_C: -40°C; Dropout Voltage: 0.75V; Accuracy Percentage: 1%; Output Voltage: 0.8-14.6V; TJmax_C: +150°C
U6 = CMP-0120008-1: Automotive-grade, single, 40-V, 4.5-MHz, low-power operational amplifier 5-SOT-23 -40 to 125; Manufacturer: Texas Instruments; Nominal Supply Current: 560uA; Standoff Height: 0mm; Max Supply Voltage: 40V; TaMin_C: -40°C; Gain Bandwidth: 4.5MHz; Input Offset Voltage: 0.125mV; Output Current Per Channel: 75mA; SizeZ_mm: 1.45mm; Min Supply Voltage: 2.7V; Voltage Gain: 145dB; TaMax_C: +125°C; Min Dual Supply Voltage: 1.35V; AEC Qualified: Yes; Input Bias Current: 0.00001uA; Max Dual Supply Voltage: 20V; Number Of Channels: 1; TJmax_C: +150°C; AEC Grade: Grade 1; Response Time: 2.5us
U7 = CMP-0084585-1: Micropower, 18V Window Comparator with 400mV Reference, DDC0006A (SOT-23-THIN-6); Alternate PartNumber: TLV6700DDCT; Alternate Manufacturer: Texas Instruments; SizeY_mm: 2.95; Rating: Catalog; SizeX_mm: 1.65; CompType: IC; SizeArea_mm2: 4.8675; SizeAreaWB_mm2: 10.4675; AEC Qualified: N; SizeZ_mm: 0.87; AEC Category: Q200
U8 = CMP-0050540-1: Automotive Catalog Quadruple 2-Input Positive-NOR Gates, PW0014A, LARGE T&R; Manufacturer: Texas Instruments; Generic Part Number: SN74AHC02-Q1; ICC @ Nom Voltage(Max)(mA): 0.02; VCC(Min)(V): 2; F @ Nom Voltage(Max)(Mhz): 110; Bits(#): 4; Voltage(Nom)(V): 3.3,5; Input Type: CMOS; VCC(Max)(V): 5.5; tpd @ Nom Voltage(Max)(ns): 13,8.5; Output Drive (IOL/IOH)(Max)(mA): 50/-50

## Sheet INA237.SchDoc
size A4; Date: Not shown in title block; ApprovedBy: Not shown in title block; CheckedBy: Not shown in title block; Author: Not shown in title block; CompanyName: Not shown in title block; Engineer: Not shown in title block; Organization: Not shown in title block; Address1: Not shown in title block; Address2: Not shown in title block; Address3: Not shown in title block; Address4: Not shown in title block; DocumentNumber: 17; Revision: Use project parameter SCH_Rev; SheetNumber: 17; SheetTotal: 19; PageSetup: Record=PageOptions¦CenterHorizontal=True¦CenterVertical=True¦PrintScale=0.93¦XCorrection=1.00¦YCorrection=1.00¦PrintKind=0¦BorderSize=5000000¦LeftOffset=0¦BottomOffset=0¦Orientation=2¦PaperLength=1000¦PaperWidth=1000¦Scale=100¦PaperSource=15¦PrintQuality=600¦MediaType=1¦DitherType=10¦PaperKind=Letter¦PrintScaleMode=1
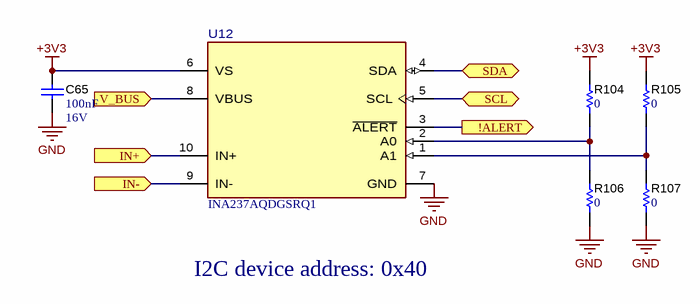
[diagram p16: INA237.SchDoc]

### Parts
C65  Cap_F: 100nF  VDC_V: 16V  [0402S]  (hidden comment: C0402C104K4RACAUTO)
R104  ValueDisplayed: 0  [0402S]  (hidden comment: RK73Z1ETTP)
R105  ValueDisplayed: 0  [0402S]  (hidden comment: RK73Z1ETTP)
R106  ValueDisplayed: 0  [0402S]  (hidden comment: RK73Z1ETTP)
R107  ValueDisplayed: 0  [0402S]  (hidden comment: RK73Z1ETTP)
U12  INA237AQDGSRQ1  [DGS0010A-MFG]

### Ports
!ALERT (out), IN+ (in), IN- (in), SCL (bidir), SDA (bidir), V_BUS (in)

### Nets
+3V3: C65.1 R104.1 R105.1 U12.6(VS)
GND: C65.2 R106.2 R107.2 U12.7(GND) U12.9(IN-) ; port IN-
!ALERT: U12.3(~{ALERT}) ; port !ALERT
PoDL_D+: U12.8(VBUS) ; port V_BUS
PoDL_D-: U12.10(IN+) ; port IN+
SCL: U12.5(SCL) ; port SCL
SDA: U12.4(SDA) ; port SDA
NetR104_2: R104.2 R106.1 U12.2(A0)
NetR105_2: R105.2 R107.1 U12.1(A1)

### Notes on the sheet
- I2C device address: 0x40

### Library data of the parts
C65 = CMP-0006237-2: as C63 on sheet High_side_switch
R104-R107 = CMP-0027007-2: as R34 on sheet 1V0_LDO
U12 = CMP-0088571-2: High-Voltage, Zero-Drift, 16-Bit ADC, I 2C, Bidirectional Shunt Current, Bus Voltage, Power, and Temperature Monitor; Manufacturer: Texas Instruments; Number Of Converters: 1; AEC Category: Q200; CompType: IC; Standoff Height: 0.05mm; Interface: I2C; Data Polarity: Differential; SizeZ_mm: 1.1mm

## Sheet GPIO_EXPANDER.SchDoc
size A4; Date: Not shown in title block; ApprovedBy: Not shown in title block; CheckedBy: Not shown in title block; Author: Not shown in title block; CompanyName: Not shown in title block; Engineer: Not shown in title block; Organization: Not shown in title block; Address1: Not shown in title block; Address2: Not shown in title block; Address3: Not shown in title block; Address4: Not shown in title block; DocumentNumber: 13; Revision: Use project parameter SCH_Rev; SheetNumber: 13; SheetTotal: 19; PageSetup: Record=PageOptions¦CenterHorizontal=True¦CenterVertical=True¦PrintScale=0.93¦XCorrection=1.00¦YCorrection=1.00¦PrintKind=0¦BorderSize=5000000¦LeftOffset=0¦BottomOffset=0¦Orientation=2¦PaperLength=1000¦PaperWidth=1000¦Scale=100¦PaperSource=15¦PrintQuality=600¦MediaType=1¦DitherType=10¦PaperKind=Letter¦PrintScaleMode=1
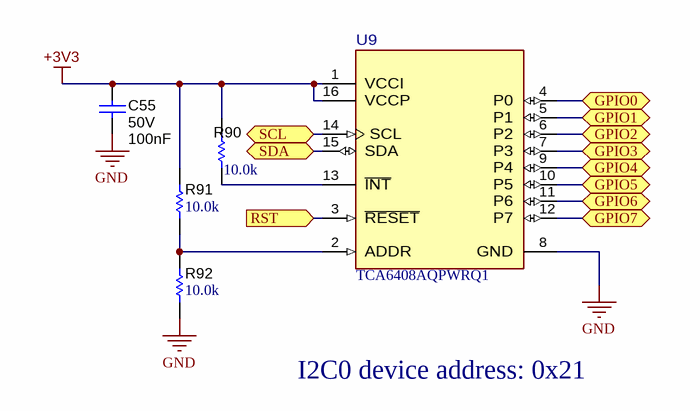
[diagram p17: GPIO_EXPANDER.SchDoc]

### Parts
C55  VDC_V: 50V  ValueDisplayed: 100nF  [0402S]  (hidden comment: C1005X5R1H104K050BB)
R90  ValueDisplayed: 10.0k  [0402S]  (hidden comment: RMCF0402FT10K0)
R91  ValueDisplayed: 10.0k  [0402S]  (hidden comment: RMCF0402FT10K0)
R92  ValueDisplayed: 10.0k  [0402S]  (hidden comment: RMCF0402FT10K0)
U9  TCA6408AQPWRQ1  [PW0016A-MFG]

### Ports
GPIO0 (bidir), GPIO1 (bidir), GPIO2 (bidir), GPIO3 (bidir), GPIO4 (bidir), GPIO5 (bidir), GPIO6 (bidir), GPIO7 (bidir), RST (in), SCL (bidir), SDA (bidir)

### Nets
+3V3: C55.2 R90.1 R91.2 U9.1(VCCI) U9.16(VCCP)
GND: C55.1 R92.1 U9.8(GND)
AE_RESET_N: U9.3(~{RESET}) ; port RST
comp_out: U9.10(P5) ; port GPIO5
EN_detection_SoC: U9.9(P4) ; port GPIO4
GPIO6: U9.11(P6) ; port GPIO6
GPIO7: U9.12(P7) ; port GPIO7
HSS_EN: U9.4(P0) ; port GPIO0
HSS_FAULT: U9.7(P3) ; port GPIO3
HSS_SNS: U9.6(P2) ; port GPIO2
Q: U9.5(P1) ; port GPIO1
SCL: U9.14(SCL) ; port SCL
SDA: U9.15(SDA) ; port SDA
NetR90_2: R90.2 U9.13(~{INT})
NetR91_1: R91.1 R92.2 U9.2(ADDR)

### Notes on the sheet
- I2C0 device address: 0x21

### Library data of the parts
C55 = CMP-0006279-2: CAP, CERM, 0.1 uF, 50 V, +/- 10%, X5R, 0402; Manufacturer: TDK; TaMin_C: -55°C; ESR_ohm: 0.039064; Polarized: N; SizeAreaWB_mm2: 3; Value1: 0.039064 ohm; U/M: EA; Value: 0.1uF; TaMax_C: 85°C; SizeZ_mm: 0.6; SizeX_mm: 1; SizeY_mm: 0.5; Cap_Case: 0402; IRMS_A: 814.669mA; AEC Category: Q200
R90-R92 = CMP-0026754-1: RES, 10.0 k, 1%, 0.063 W, AEC-Q200 Grade 0, 0402; Manufacturer: Stackpole Electronics Inc; Power_W: 63mW; TempCo: 100 ppm/C; Value_Code: 10k0; U/M: EA; Value: 10.0k; EIA_Code: E96; Res_ohm: 10k; SizeX_mm: 1; SizeY_mm: 0.5; SizeZ_mm: 0.6; Value2: 0.063W; AEC Qualified: Y; VDC_V: 50V; AEC Category: Q200; AEC Grade: 0
U9 = CMP-0091949-1: IC I/O EXPANDER I2C 8B 16TSSOP; Manufacturer: Texas Instruments; TJmax_C: +135°C; AEC Qualified: No; TaMin_C: -40°C; Max Supply Voltage: 3.6V; SizeZ_mm: 1.2mm; Nominal Supply Current: 9mA; Number Of I/Os: 8; Min Supply Voltage: 1.65V; TaMax_C: +125°C; Standoff Height: 0.05mm; Frequency_Fixed: 400kHz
